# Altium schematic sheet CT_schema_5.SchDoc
size 349 x 348 mm
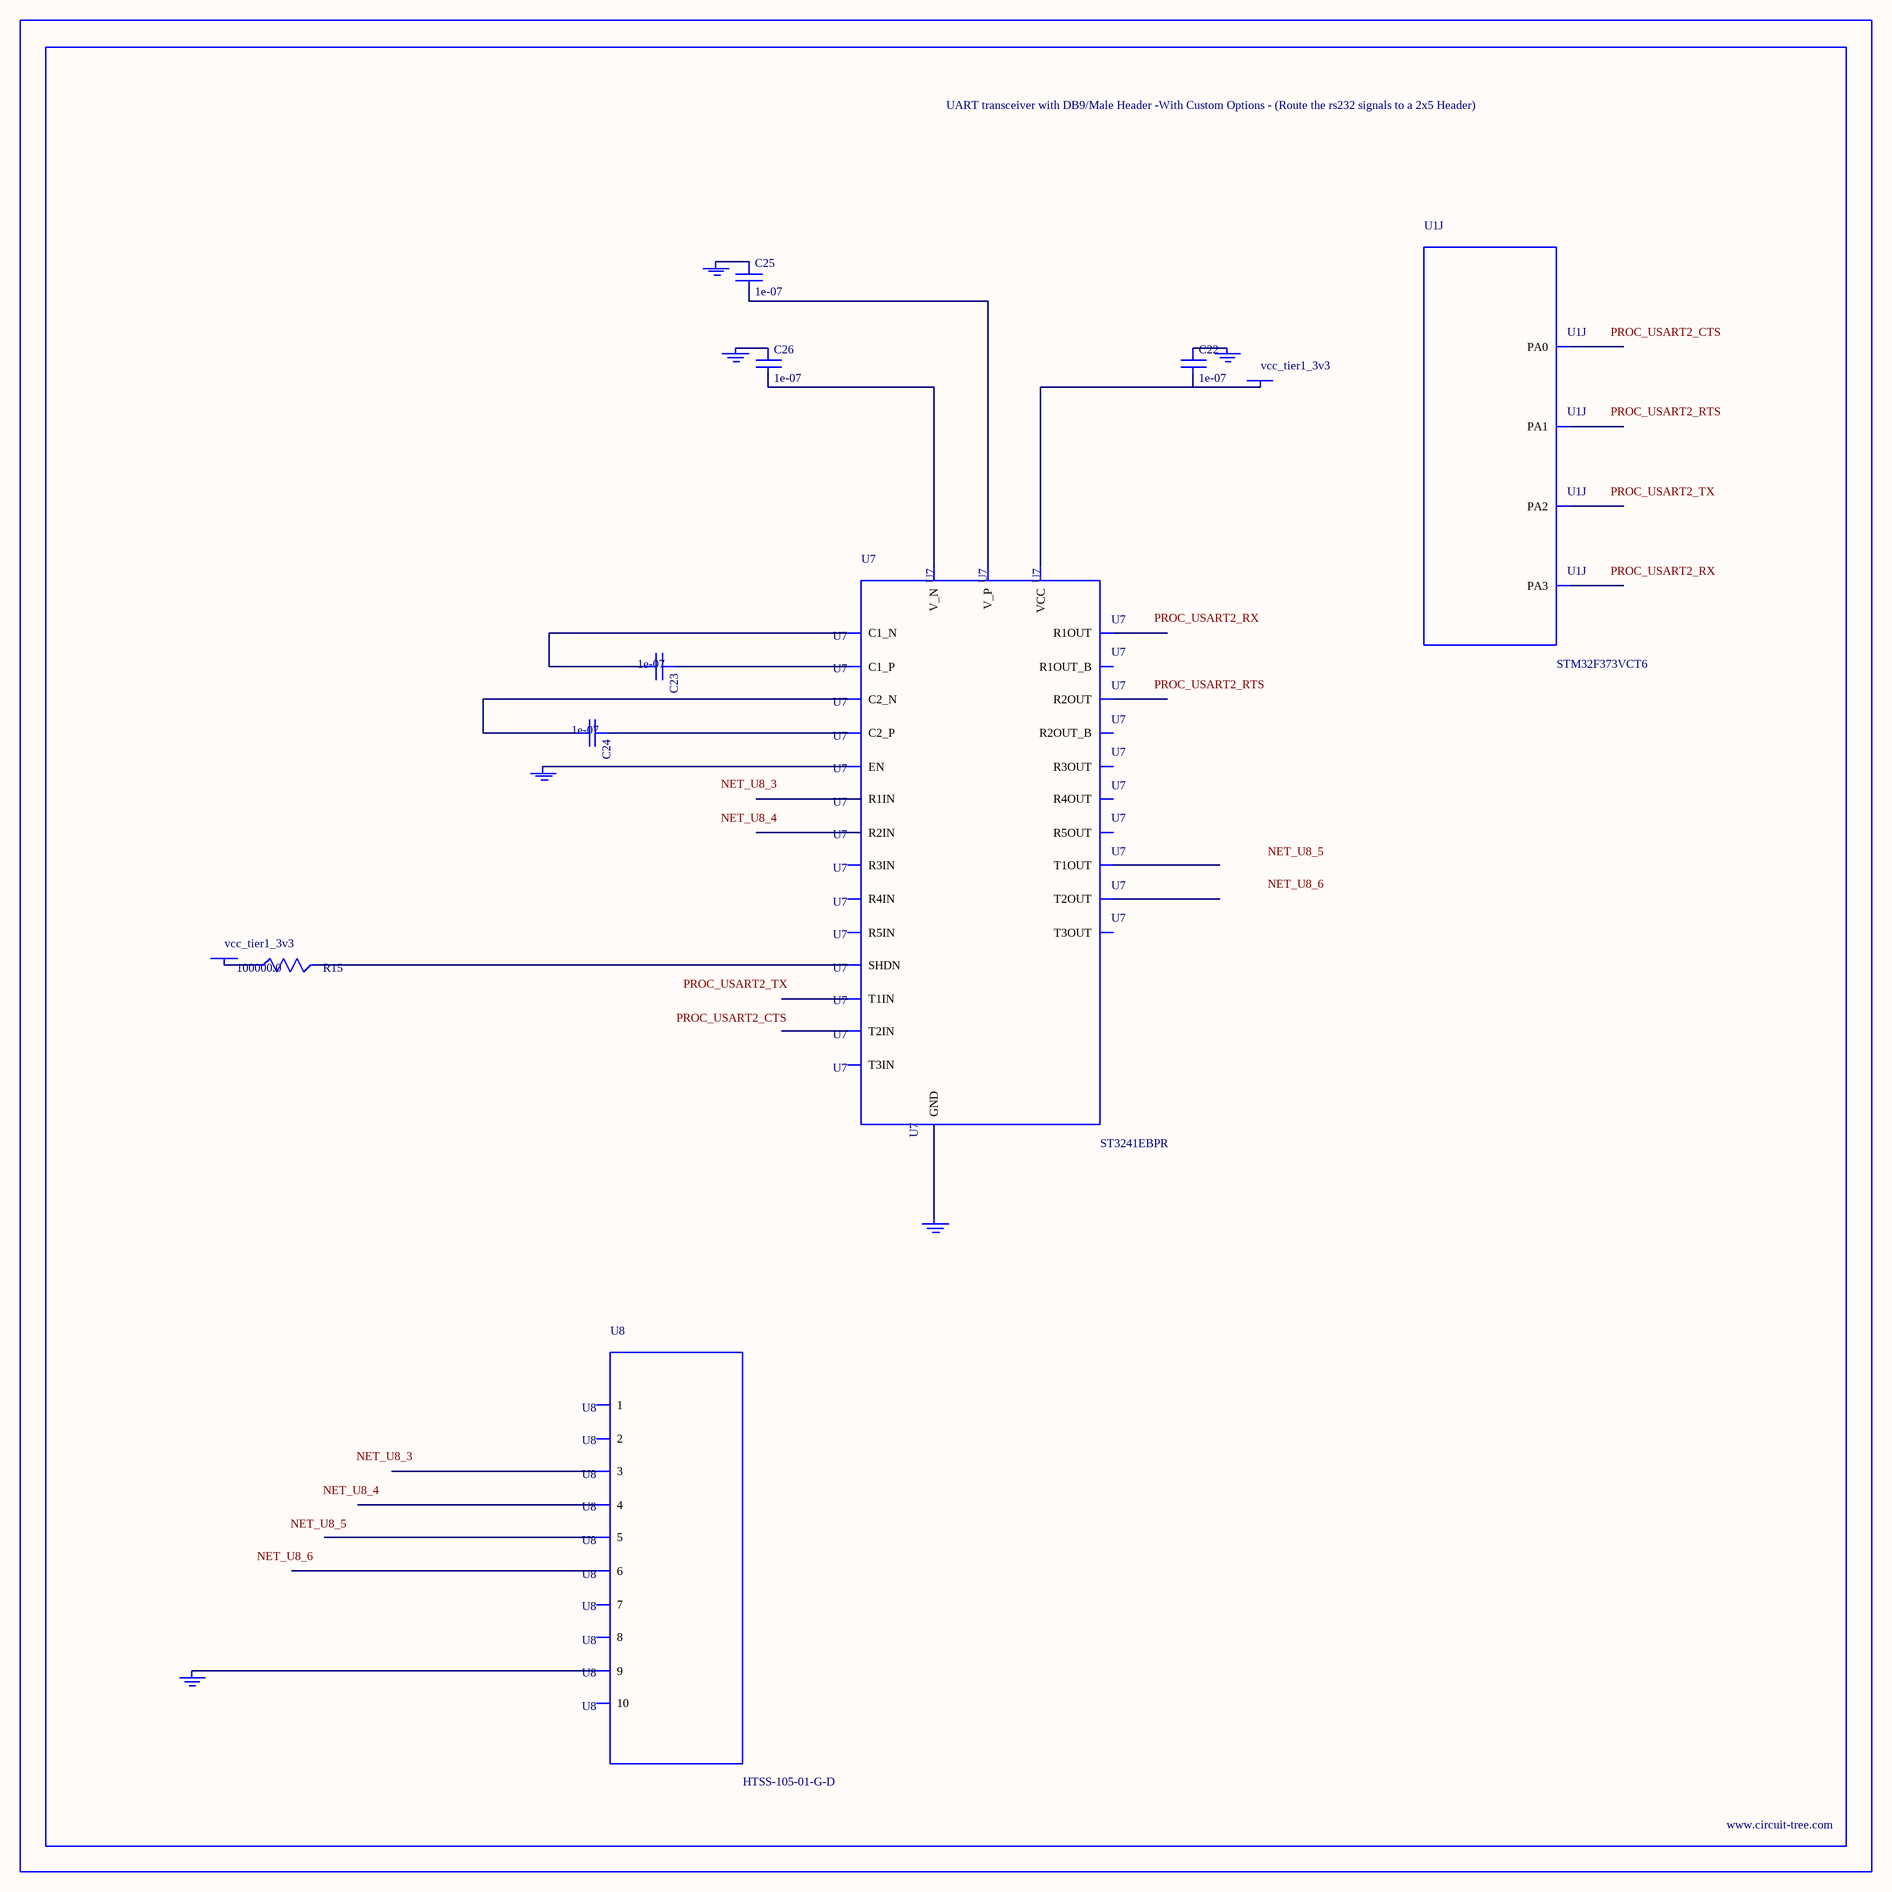
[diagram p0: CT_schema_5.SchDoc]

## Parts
BORDER4  (no value)
C22  1e-07  [C0402]
C23  1e-07  [C0402]
C24  1e-07  [C0402]
C25  1e-07  [C0402]
C26  1e-07  [C0402]
GND_INSTANCE_4_0  (no value)
GND_INSTANCE_4_1  (no value)
GND_INSTANCE_4_2  (no value)
GND_INSTANCE_4_3  (no value)
GND_INSTANCE_4_4  (no value)
GND_INSTANCE_4_5  (no value)
POWER_INSTANCE_4_0  vcc_tier1_3v3
POWER_INSTANCE_4_1  vcc_tier1_3v3
R15  100000.0  [R0603]
U1  STM32F373VCT6  [LQFP100]  (part J of 10)
U7  ST3241EBPR  [SSOP-28]
U8  HTSS-105-01-G-D  [HTSS-105-01-G-D]

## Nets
NetC22_1: C22.1 GND_INSTANCE_4_2.0(GND)
NetC22_2: C22.2 POWER_INSTANCE_4_1.0(PWR) U7.26(VCC)
NetC23_1: C23.1 U7.28(C1_P)
NetC23_2: C23.2 U7.24(C1_N)
NetC24_1: C24.1 U7.1(C2_P)
NetC24_2: C24.2 U7.2(C2_N)
NetC25_1: C25.1 GND_INSTANCE_4_3.0(GND)
NetC25_2: C25.2 U7.27(V_P)
NetC26_1: C26.1 GND_INSTANCE_4_0.0(GND)
NetC26_2: C26.2 U7.3(V_N)
NetGND_INSTANCE_4_1_0: GND_INSTANCE_4_1.0(GND) U7.23(EN)
NetGND_INSTANCE_4_4_0: GND_INSTANCE_4_4.0(GND) U7.25(GND)
NetGND_INSTANCE_4_5_0: GND_INSTANCE_4_5.0(GND) U8.9
NetPOWER_INSTANCE_4_0_0: POWER_INSTANCE_4_0.0(PWR) R15.1
NetR15_2: R15.2 U7.22(SHDN)

Not connected (* = marked no-connect by the designer): U1 23(PA0) 24(PA1) 25(PA2) 26(PA3); U7 4(R1IN) 5(R2IN) 6(R3IN) 7(R4IN) 8(R5IN) 9(T1OUT) 10(T2OUT) 11(T3OUT) 12(T3IN) 13(T2IN) 14(T1IN) 15(R5OUT) 16(R4OUT) 17(R3OUT) 18(R2OUT) 19(R1OUT) 20(R2OUT_B) 21(R1OUT_B); U8 1 2 3 4 5 6 7 8 10

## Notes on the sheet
- Labels drawn without touching a wire or pin: NET_U8_3, NET_U8_4, NET_U8_5, NET_U8_6, PROC_USART2_CTS, PROC_USART2_RTS, PROC_USART2_RX, PROC_USART2_TX

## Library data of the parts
BORDER4 = BORDER_PAGE4
C22-C26 = C0402C104K3RACTU
GND_INSTANCE_4_0-GND_INSTANCE_4_5 = GND
POWER_INSTANCE_4_0 POWER_INSTANCE_4_1 = PWR
R15 = RC0603JR-07100KL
